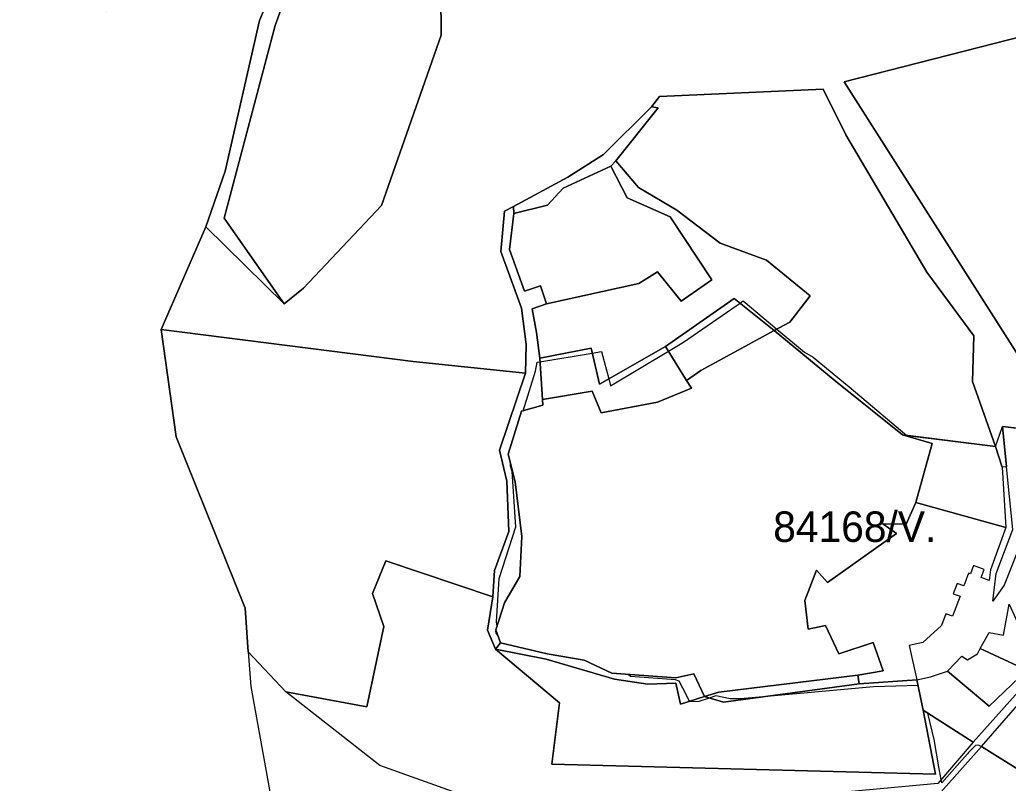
# Model space of a CAD drawing. Extents: x -477304 to -465429, y -1159113 to -1149210.
# Drawn here: x -474610.4 to -474123.8, y -1153825.1 to -1153449.4 of the extents above; entities that cross this region are included whole.
import ezdxf

# ---------------------------------------------------------------- set-up
doc = ezdxf.new("R2010")
doc.units = 0
for name, color, linetype in [('BPEJ_s', 7, 'Continuous'), ('PUPFL_s', 7, 'Continuous'), ('trav_porost_s', 7, 'Continuous'), ('zahrada_s', 7, 'Continuous')]:
    doc.layers.add(name, color=color, linetype=linetype)

msp = doc.modelspace()

# ---------------------------------------------------------------- linework, layer by layer
at = {"layer": 'BPEJ_s'}
msp.add_line((-474255.78, -1153588.83), (-474254.32, -1153587.82), dxfattribs=at)
for points in [[(-474108.57, -1153824.77), (-474136.96, -1153807.1), (-474138.55, -1153806.41), (-474138.61, -1153806.38), (-474139.89, -1153806.59), (-474143.3, -1153810), (-474143.91, -1153810.68), (-474151.59, -1153819.36), (-474156.55, -1153824.95), (-474156.83, -1153823.36), (-474157.76, -1153818.08), (-474160.32, -1153803.61), (-474163.42, -1153790.65), (-474165.65, -1153789.22), (-474168.23, -1153777.02), (-474190.11, -1153777.65), (-474217.17, -1153780.11), (-474242.73, -1153782.44), (-474255.64, -1153783.61), (-474260.75, -1153783.61), (-474267.77, -1153782.12), (-474271.03, -1153783.21), (-474276.07, -1153784.89), (-474280.56, -1153785.15), (-474280.72, -1153784.84), (-474283.94, -1153778.29), (-474285.86, -1153774.89), (-474287.56, -1153774.25), (-474309.69, -1153772.55), (-474310.94, -1153771.61), (-474318.97, -1153771.05), (-474332.57, -1153764.64), (-474350.86, -1153761.54), (-474373.68, -1153756.07), (-474374.84, -1153752.81), (-474375.39, -1153751.98), (-474375.86, -1153751.27), (-474376.08, -1153750.2), (-474375.86, -1153749.92), (-474375.98, -1153749.59), (-474375.41, -1153747.8), (-474375.65, -1153745.74), (-474374.37, -1153724.46), (-474366.29, -1153698.92), (-474367.99, -1153671.69), (-474368.84, -1153669.14), (-474368.81, -1153667.81), (-474369.97, -1153663.26), (-474363.35, -1153642.07), (-474362.58, -1153641.86), (-474356.5, -1153622.32), (-474355.67, -1153617.93), (-474354.34, -1153617.71), (-474328.63, -1153613.49), (-474324.03, -1153612.73), (-474322.76, -1153617.55), (-474320.48, -1153626.17), (-474319.59, -1153629.5), (-474291.12, -1153612.48), (-474283.73, -1153608.07), (-474257.77, -1153590.19), (-474255.78, -1153588.83)], [(-474368.84, -1153669.14), (-474368.81, -1153667.81), (-474369.97, -1153663.26), (-474363.35, -1153642.07), (-474362.58, -1153641.86), (-474356.5, -1153622.32), (-474355.67, -1153617.93), (-474354.34, -1153617.71), (-474328.63, -1153613.49), (-474324.03, -1153612.73), (-474322.76, -1153617.55), (-474320.48, -1153626.17), (-474319.59, -1153629.5), (-474291.12, -1153612.48), (-474283.73, -1153608.07), (-474257.77, -1153590.19), (-474255.78, -1153588.83), (-474254.32, -1153587.82), (-474237.74, -1153601.64), (-474224.15, -1153612.96), (-474219.9, -1153615.51), (-474201.17, -1153630.83), (-474173.75, -1153654.02), (-474130.08, -1153659.38), (-474126.65, -1153649.57), (-474102.8, -1153652.34)], [(-474254.32, -1153587.82), (-474237.74, -1153601.64), (-474224.15, -1153612.96), (-474219.9, -1153615.51), (-474201.17, -1153630.83), (-474173.75, -1153654.02)], [(-474173.75, -1153654.02), (-474130.08, -1153659.38), (-474126.65, -1153649.57), (-474102.8, -1153652.34)], [(-474108.57, -1153824.77), (-474136.96, -1153807.1), (-474138.55, -1153806.41), (-474138.61, -1153806.38), (-474139.89, -1153806.59), (-474143.3, -1153810), (-474143.91, -1153810.68), (-474151.59, -1153819.36), (-474156.55, -1153824.95), (-474156.83, -1153823.36), (-474157.76, -1153818.08), (-474160.32, -1153803.61), (-474163.42, -1153790.65), (-474165.65, -1153789.22), (-474168.23, -1153777.02), (-474190.11, -1153777.65), (-474217.17, -1153780.11), (-474242.73, -1153782.44), (-474255.64, -1153783.61), (-474260.75, -1153783.61), (-474267.77, -1153782.12), (-474271.03, -1153783.21), (-474276.07, -1153784.89), (-474280.56, -1153785.15), (-474280.72, -1153784.84), (-474283.94, -1153778.29), (-474285.86, -1153774.89), (-474287.56, -1153774.25), (-474309.69, -1153772.55), (-474310.94, -1153771.61), (-474318.97, -1153771.05), (-474332.57, -1153764.64), (-474350.86, -1153761.54), (-474373.68, -1153756.07), (-474374.84, -1153752.81), (-474375.39, -1153751.98), (-474375.86, -1153751.27), (-474376.08, -1153750.2), (-474375.86, -1153749.92), (-474375.98, -1153749.59), (-474375.41, -1153747.8), (-474375.65, -1153745.74), (-474374.37, -1153724.46), (-474366.29, -1153698.92), (-474367.99, -1153671.69), (-474368.84, -1153669.14)]]:
    msp.add_lwpolyline(points, dxfattribs=at)
at = {"layer": 'PUPFL_s'}
for points in [[(-474509.83, -1153546.98), (-474480.21, -1153589.27), (-474518.88, -1153551.35), (-474509.3, -1153523.93), (-474492.45, -1153449.81), (-474485.08, -1153432.01), (-474470.16, -1153380.87), (-474458.87, -1153383.47), (-474467.36, -1153408.17), (-474477.58, -1153432.55), (-474484.71, -1153452.21)], [(-474509.83, -1153546.98), (-474484.71, -1153452.21), (-474477.58, -1153432.55), (-474467.36, -1153408.17), (-474458.87, -1153383.47), (-474403.5, -1153395.97), (-474402.9, -1153457.05), (-474432.41, -1153540.84), (-474470.78, -1153581.5), (-474480.21, -1153589.27)], [(-474071.42, -1153491.25), (-474073.88, -1153503.03), (-474071.34, -1153514.17), (-474077.43, -1153556.38), (-474074.55, -1153599.65), (-474069.67, -1153631.47), (-474113.87, -1153622.53), (-474204.61, -1153479.97), (-474101.15, -1153453.48), (-474081.71, -1153480.95)], [(-474175.9, -1153653.76), (-474208.94, -1153627.19), (-474239.03, -1153602.31), (-474231.33, -1153598.27), (-474221.32, -1153585.31), (-474242.85, -1153567.78), (-474265.66, -1153559.31), (-474286.97, -1153543.11), (-474305.83, -1153531.91), (-474317.06, -1153518.88), (-474296.08, -1153492.68), (-474299.46, -1153492.27), (-474295.47, -1153487.23), (-474214.99, -1153483.5), (-474203.83, -1153506.06), (-474163.81, -1153573.57), (-474140.77, -1153604.94), (-474141.42, -1153627.44), (-474130.08, -1153659.38)], [(-474296.08, -1153492.68), (-474317.06, -1153518.88), (-474319.4, -1153521.52), (-474342.97, -1153532.25), (-474350.64, -1153540.64), (-474367.16, -1153544.78), (-474367.41, -1153541.31), (-474340.6, -1153526.92), (-474323, -1153515.8), (-474299.46, -1153492.27)], [(-474350.64, -1153540.64), (-474342.97, -1153532.25), (-474319.4, -1153521.52), (-474311.37, -1153536.99), (-474290.21, -1153546.48), (-474269.7, -1153577.44), (-474284.85, -1153587.96), (-474296.44, -1153573.54), (-474305.72, -1153579.23), (-474351.18, -1153589.25), (-474354.06, -1153580.36), (-474362.01, -1153582.95), (-474369.32, -1153562.52), (-474367.16, -1153544.78)], [(-474329.19, -1153611.06), (-474354.46, -1153615.97), (-474356, -1153603.39), (-474358.09, -1153591.61), (-474351.18, -1153589.25), (-474305.72, -1153579.23), (-474296.44, -1153573.54), (-474284.85, -1153587.96), (-474269.7, -1153577.44), (-474290.21, -1153546.48), (-474311.37, -1153536.99), (-474319.4, -1153521.52), (-474317.06, -1153518.88), (-474305.83, -1153531.91), (-474286.97, -1153543.11), (-474265.66, -1153559.31), (-474242.85, -1153567.78), (-474221.32, -1153585.31), (-474231.33, -1153598.27), (-474239.03, -1153602.31), (-474258.65, -1153586.52), (-474292.48, -1153610.25), (-474325.09, -1153628.79)], [(-474352.84, -1153639.13), (-474363.35, -1153642.07), (-474369.97, -1153663.26), (-474366.48, -1153676.89), (-474363.31, -1153703.68), (-474364.25, -1153723.34), (-474371.73, -1153736.34), (-474375.98, -1153749.59), (-474373.68, -1153756.07), (-474376.19, -1153759.24), (-474380.23, -1153749.81), (-474377.49, -1153733.46), (-474376.7, -1153720.53), (-474369.64, -1153701.3), (-474370.58, -1153676.57), (-474374.32, -1153661.23), (-474361.47, -1153623.28), (-474361.19, -1153609.24), (-474363.49, -1153591.27), (-474373.64, -1153563.46), (-474371.73, -1153543.63), (-474367.41, -1153541.31), (-474367.16, -1153544.78), (-474369.32, -1153562.52), (-474362.01, -1153582.95), (-474354.06, -1153580.36), (-474351.18, -1153589.25), (-474358.09, -1153591.61), (-474356, -1153603.39), (-474354.46, -1153615.97), (-474353.04, -1153636.31)], [(-474239.03, -1153602.31), (-474275.2, -1153622.02), (-474282.26, -1153626.97), (-474292.48, -1153610.25), (-474258.65, -1153586.52)], [(-474376.7, -1153720.53), (-474377.49, -1153733.46), (-474430.18, -1153715.62), (-474436.77, -1153731.84), (-474431.26, -1153747.95), (-474439.61, -1153787.63), (-474479.42, -1153780.18), (-474497.93, -1153760.48), (-474499.53, -1153738.99), (-474533.35, -1153654.71), (-474540.81, -1153601.85), (-474416.68, -1153617.52), (-474361.47, -1153623.28), (-474374.32, -1153661.23), (-474370.58, -1153676.57), (-474369.64, -1153701.3)], [(-474279.81, -1153630.69), (-474296.47, -1153637.57), (-474324.15, -1153642.81), (-474328.69, -1153632.23), (-474353.04, -1153636.31), (-474354.46, -1153615.97), (-474329.19, -1153611.06), (-474325.09, -1153628.79), (-474292.48, -1153610.25), (-474282.26, -1153626.97)], [(-474344.65, -1153785.64), (-474348.44, -1153815.74), (-474159.59, -1153820.68), (-474165.65, -1153789.22), (-474141, -1153804.98), (-474158.44, -1153825.22), (-474357.1, -1153843.71), (-474433.16, -1153816.42), (-474479.42, -1153780.18), (-474439.61, -1153787.63), (-474431.26, -1153747.95), (-474436.77, -1153731.84), (-474430.18, -1153715.62), (-474377.49, -1153733.46), (-474380.23, -1153749.81), (-474376.19, -1153759.24)], [(-474350.86, -1153761.54), (-474332.57, -1153764.64), (-474318.97, -1153771.05), (-474287.44, -1153773.25), (-474278.59, -1153771.38), (-474273.26, -1153782.54), (-474285.17, -1153786.21), (-474287.4, -1153775.95), (-474301.26, -1153776.39), (-474317.57, -1153773.88), (-474351.23, -1153764.05), (-474376.19, -1153759.24), (-474373.68, -1153756.07)], [(-474159.59, -1153820.68), (-474348.44, -1153815.74), (-474344.65, -1153785.64), (-474376.19, -1153759.24), (-474351.23, -1153764.05), (-474317.57, -1153773.88), (-474301.26, -1153776.39), (-474287.4, -1153775.95), (-474285.17, -1153786.21), (-474273.26, -1153782.54), (-474263.98, -1153785.32), (-474197.13, -1153776.25), (-474168.81, -1153774.27), (-474165.65, -1153789.22)], [(-474273.26, -1153782.54), (-474266.35, -1153780.34), (-474197.84, -1153771.95), (-474197.13, -1153776.25), (-474263.98, -1153785.32)], [(-474037.94, -1153843.41), (-474062.65, -1153846.11), (-474075.98, -1153856.54), (-474084.14, -1153854.43), (-474165.39, -1153867.04), (-474202.37, -1153879.94), (-474227.94, -1153885.74), (-474290.58, -1153895.88), (-474303.54, -1153897.14), (-474363.35, -1153892.8), (-474392.23, -1153904.09), (-474390.13, -1153878.32), (-474370.15, -1153871.7), (-474362.3, -1153848.71), (-474157.02, -1153829.56), (-474136.98, -1153807.12), (-474108.57, -1153824.77), (-474081.96, -1153823), (-474074.89, -1153822.51), (-474056.44, -1153817.67), (-474036.68, -1153825.64), (-474033.65, -1153833.96), (-474035.67, -1153838.41)]]:
    msp.add_lwpolyline(points, close=True, dxfattribs=at)
for points in [[(-474093.46, -1153653.42), (-474126.65, -1153649.57), (-474124.63, -1153669.37), (-474126.72, -1153669.59), (-474130.08, -1153659.38), (-474141.42, -1153627.44), (-474140.77, -1153604.94), (-474163.81, -1153573.57), (-474203.83, -1153506.06), (-474214.99, -1153483.5), (-474295.47, -1153487.23), (-474299.46, -1153492.27), (-474323, -1153515.8), (-474340.6, -1153526.92), (-474367.41, -1153541.31), (-474371.73, -1153543.63), (-474373.64, -1153563.46), (-474363.49, -1153591.27), (-474361.19, -1153609.24), (-474361.47, -1153623.28), (-474416.68, -1153617.52), (-474540.81, -1153601.85), (-474518.88, -1153551.35), (-474480.21, -1153589.27), (-474470.78, -1153581.5), (-474432.41, -1153540.84), (-474402.9, -1153457.05), (-474403.5, -1153395.97)], [(-474646.08, -1153441.03), (-474567.93, -1153445.36), (-474550.25, -1153410.01), (-474485.08, -1153432.01), (-474492.45, -1153449.81), (-474509.3, -1153523.93), (-474518.88, -1153551.35), (-474540.81, -1153601.85), (-474533.35, -1153654.71), (-474499.53, -1153738.99), (-474497.93, -1153760.48), (-474496.66, -1153777.51), (-474486.58, -1153833.06), (-474480.82, -1153852.82), (-474465.31, -1153877.98), (-474446.36, -1153908.71), (-474456.98, -1153909.49), (-474479.93, -1153913.39), (-474509.44, -1153918.7), (-474587.46, -1153941.08), (-474628.65, -1153948.83)], [(-474101.15, -1153453.48), (-474204.61, -1153479.97), (-474113.87, -1153622.53)]]:
    msp.add_lwpolyline(points, dxfattribs=at)
at = {"layer": 'trav_porost_s'}
for points in [[(-474185.31, -1153769.83), (-474197.84, -1153771.95), (-474266.35, -1153780.34), (-474273.26, -1153782.54), (-474278.59, -1153771.38), (-474287.44, -1153773.25), (-474318.97, -1153771.05), (-474332.57, -1153764.64), (-474350.86, -1153761.54), (-474373.68, -1153756.07), (-474375.98, -1153749.59), (-474371.73, -1153736.34), (-474364.25, -1153723.34), (-474363.31, -1153703.68), (-474366.48, -1153676.89), (-474369.97, -1153663.26), (-474363.35, -1153642.07), (-474352.84, -1153639.13), (-474353.04, -1153636.31), (-474328.69, -1153632.23), (-474324.15, -1153642.81), (-474296.47, -1153637.57), (-474279.81, -1153630.69), (-474282.26, -1153626.97), (-474275.2, -1153622.02), (-474239.03, -1153602.31), (-474208.94, -1153627.19), (-474175.9, -1153653.76), (-474161.18, -1153657.91), (-474169.24, -1153687.01), (-474173.99, -1153697.7), (-474185.58, -1153697.49), (-474178.75, -1153702.31), (-474212.79, -1153726.33), (-474218.12, -1153720.28), (-474224.02, -1153735.19), (-474222.23, -1153749.29), (-474213.75, -1153747.52), (-474207.16, -1153761.5), (-474190.25, -1153755.88)], [(-474125.83, -1153727.69), (-474131.38, -1153735.49), (-474129.72, -1153721.86), (-474121.59, -1153700.3), (-474124.63, -1153669.37), (-474126.65, -1153649.57), (-474093.46, -1153653.42), (-474110.62, -1153697.28), (-474119.24, -1153711.06)], [(-474169.24, -1153687.01), (-474161.18, -1153657.91), (-474175.9, -1153653.76), (-474130.08, -1153659.38), (-474126.72, -1153669.59), (-474125.01, -1153699.24)], [(-474142.35, -1153722.03), (-474143.29, -1153721.72), (-474143.62, -1153722.57), (-474143.73, -1153722.56), (-474145.36, -1153727.25), (-474145.46, -1153727.27), (-474145.63, -1153727.98), (-474148.95, -1153726.79), (-474150.93, -1153731.88), (-474147.54, -1153733.12), (-474151.21, -1153742.99), (-474154.61, -1153741.77), (-474156.73, -1153747.58), (-474165.88, -1153755.84), (-474172.57, -1153757.32), (-474168.81, -1153774.27), (-474197.13, -1153776.25), (-474197.84, -1153771.95), (-474185.31, -1153769.83), (-474190.25, -1153755.88), (-474207.16, -1153761.5), (-474213.75, -1153747.52), (-474222.23, -1153749.29), (-474224.02, -1153735.19), (-474218.12, -1153720.28), (-474212.79, -1153726.33), (-474178.75, -1153702.31), (-474185.58, -1153697.49), (-474173.99, -1153697.7), (-474169.24, -1153687.01), (-474125.01, -1153699.24), (-474132.57, -1153720.11), (-474133.27, -1153725.39), (-474137.11, -1153723.97), (-474135.62, -1153720), (-474140.88, -1153718.07)], [(-474123.38, -1153737.09), (-474114.32, -1153756.85), (-474111.62, -1153766.14), (-474111.92, -1153772.24), (-474141, -1153804.98), (-474165.65, -1153789.22), (-474168.81, -1153774.27), (-474162.12, -1153772.79), (-474153.7, -1153769.92), (-474133.15, -1153787.15), (-474114.58, -1153769.51), (-474137.6, -1153758.91), (-474133.25, -1153751.01), (-474126.08, -1153752.28)], [(-474096.72, -1153767.4), (-474103.4, -1153786.14), (-474110.93, -1153799.01), (-474108.57, -1153824.77), (-474136.98, -1153807.12), (-474107.9, -1153773.82), (-474106.87, -1153763.25), (-474108.5, -1153756.15), (-474073.38, -1153748.35), (-474079.61, -1153762.59)]]:
    msp.add_lwpolyline(points, close=True, dxfattribs=at)
at = {"layer": 'zahrada_s'}
msp.add_lwpolyline([(-474137.6, -1153758.91), (-474114.58, -1153769.51), (-474133.15, -1153787.15), (-474153.7, -1153769.92), (-474146.61, -1153762.6), (-474143.88, -1153764.34), (-474138.97, -1153761.41)], close=True, dxfattribs=at)

# ---------------------------------------------------------------- texts
at = {"layer": 'BPEJ_s'}
msp.add_text('84168/V.', height=15, dxfattribs=at).set_placement((-474239.52, -1153706.39))

doc.saveas('drawing.dxf')
